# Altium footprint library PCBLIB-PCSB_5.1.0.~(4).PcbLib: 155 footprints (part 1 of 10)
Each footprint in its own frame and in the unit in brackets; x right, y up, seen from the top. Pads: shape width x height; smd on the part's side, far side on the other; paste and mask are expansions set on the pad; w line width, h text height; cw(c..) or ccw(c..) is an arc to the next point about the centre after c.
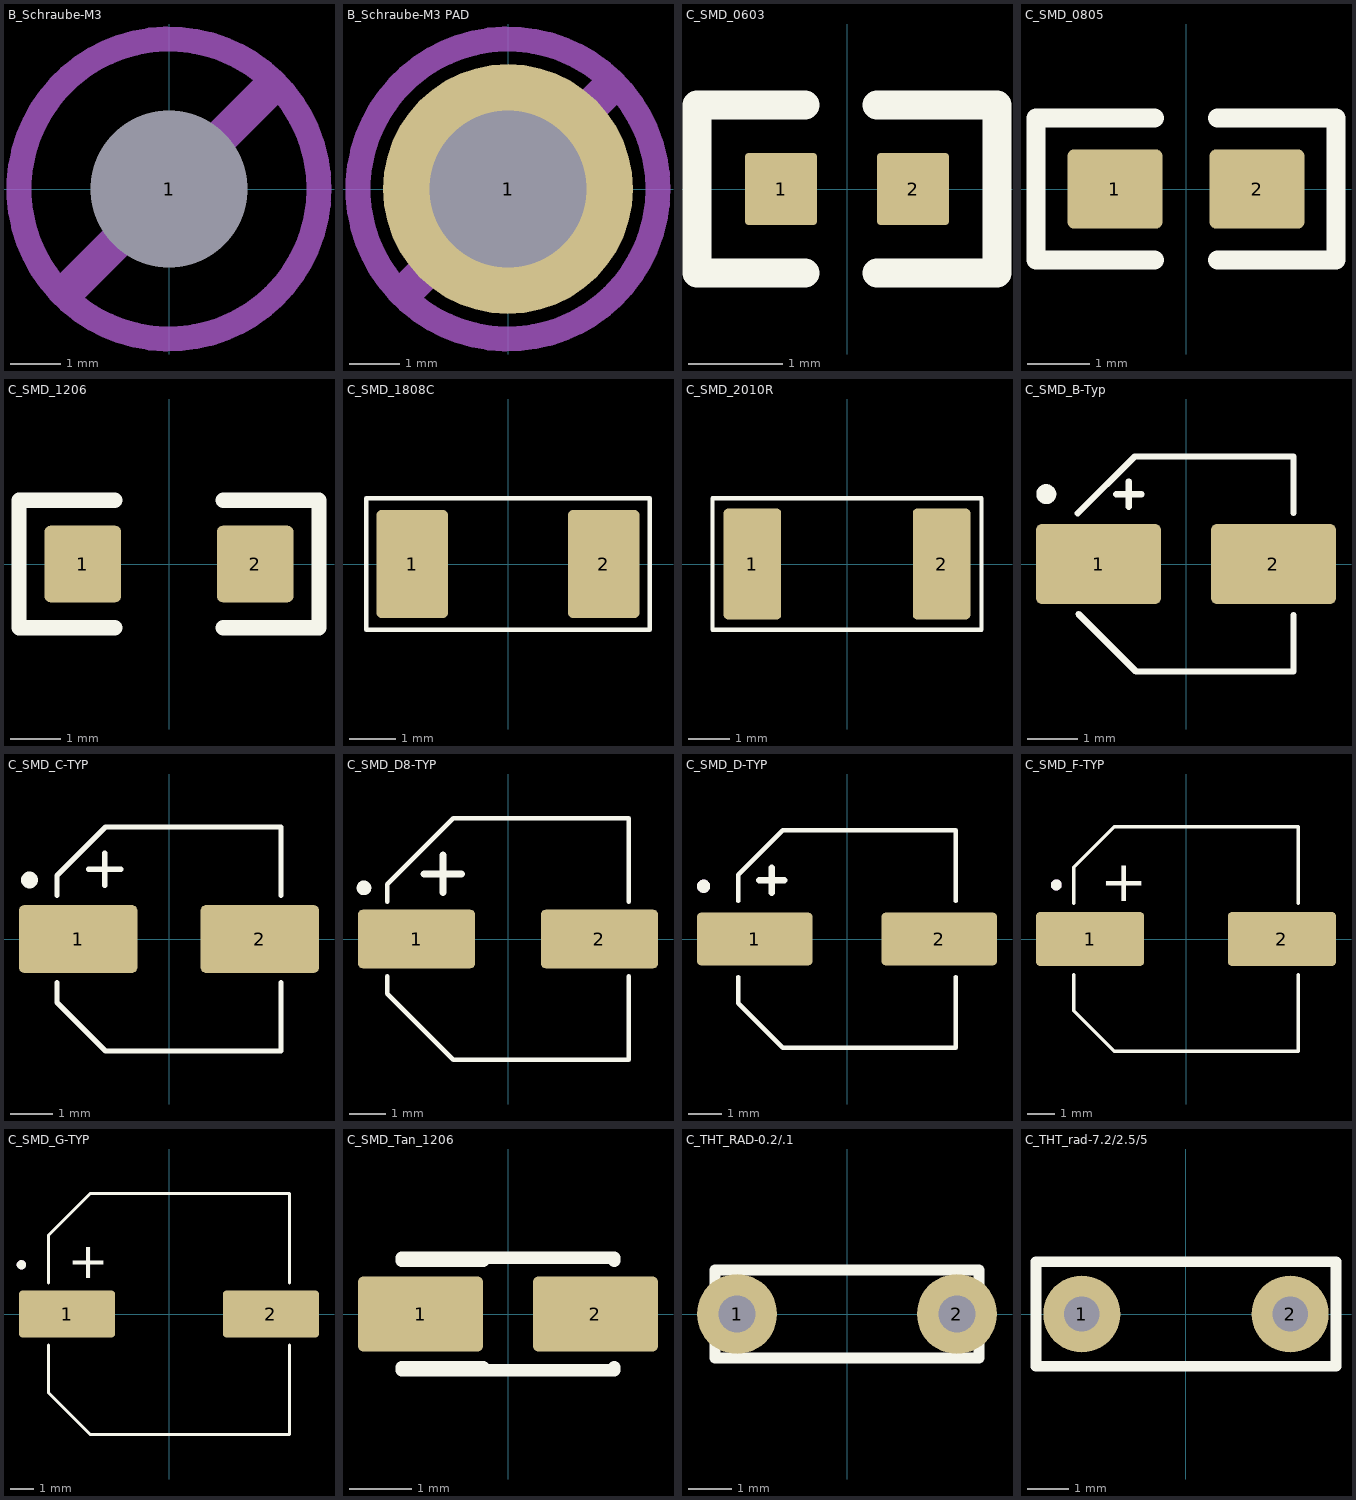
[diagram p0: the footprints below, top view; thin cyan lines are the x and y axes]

## B_Schraube-M3 [mm] "LB-2024-04-18"
pads (1):
  round 0.75 hole 3.15 unplated: 1(0,0)
Mechanical 1:
  circle w0.5: c0,0 r3
  lines w0.7: -2,-2 2,2

## B_Schraube-M3 PAD [mm] "LB-2024-04-18"
pads (1):
  round 5 hole 3.15 unplated: 1(0,0)
Mechanical 1:
  circle w0.5: c0,0 r3
  lines w0.7: -2,-2 2,2

## C_SMD_0603 [mil] "LB-2024-04-17"
pads (2):
  rrect10% 30x30 smd paste-0.79 mask+1.97: 1(-27.5,0) 2(27.5,0)
Top Overlay:
  lines w12: -17.5,-35 -62.5,-35 -62.5,35 -17.5,35 ; 12.5,-35 62.5,-35 62.5,35 12.5,35

## C_SMD_0805 [mil] "LB-2024-04-17"
pads (2):
  rrect15% 60x50 smd paste-0.79 mask+1.97: 1(-45,0) 2(45,0)
Top Overlay:
  lines w12: -20,-45 -95,-45 -95,45 -20,45 ; 20,-45 95,-45 95,45 20,45

## C_SMD_1206 [mil] "LB-2024-04-17"
pads (2):
  rrect15% 60x60 smd paste-0.79 mask+1.97: 1(-67.5,0) 2(67.5,0)
Top Overlay:
  lines w12: -42.5,-50 -117.5,-50 -117.5,50 -42.5,50 ; 42.5,-50 117.5,-50 117.5,50 42.5,50

## C_SMD_1808C [mm] "LB-2024-04-17"
height 2
pads (2):
  rrect15% 1.55x2.35 smd paste-0.02 mask+0.05: 1(-2.075,0) 2(2.075,0)
Top Overlay:
  lines w0.1: -3.075,-1.425 3.075,-1.425 3.075,1.425 -3.075,1.425 -3.075,-1.425

## C_SMD_2010R [mm] "LB-2024-04-17"
height 0.7
pads (2):
  rrect15% 1.4x2.7 smd paste-0.02 mask+0.05: 1(-2.3,0) 2(2.3,0)
Top Overlay:
  lines w0.1: -3.275,-1.6 -3.275,1.6 3.275,1.6 3.275,-1.6 -3.275,-1.6

## C_SMD_B-Typ [mm] "LB-2024-04-16"
pads (2):
  rrect15% 2.5x1.6 smd paste-0.02 mask+0.05: 1(-1.75,0) 2(1.75,0)
Top Overlay:
  circle w0.2: c-2.794,1.397 r0.1
  lines w0.127: -2.163,1.012 -1.025,2.15 2.15,2.15 2.15,1.025 ; -2.15,-1 -1,-2.15 2.15,-2.15 2.15,-1.025 ; -1.397,1.397 -0.889,1.397 ; -1.143,1.143 -1.143,1.651

## C_SMD_C-TYP [mm] "LB-2024-04-15"
pads (2):
  rrect15% 2.8x1.6 smd paste-0.02 mask+0.05: 1(-2.15,0) 2(2.15,0)
Top Overlay:
  circle w0.2: c-3.302,1.397 r0.1
  lines w0.127: -2.65,-1.033 -2.65,-1.5 -1.5,-2.65 2.65,-2.65 2.65,-1.033 ; -2.65,1.033 -2.65,1.5 ; -1.905,1.651 -1.143,1.651 ; -1.524,1.27 -1.524,2.032 ; 2.65,1.033 2.65,2.65 -1.5,2.65 ; -2.65,1.5 -1.5,2.65 ; -2.65,1.5 -1.5,2.65
3D body "EEE-FN1E470R.stp": height 0, standoff 0, extent 0,0 0,0

## C_SMD_D8-TYP [mm] "LB-2024-04-16"
pads (2):
  rrect15% 3.2x1.6 smd paste-0.02 mask+0.05: 1(-2.5,0) 2(2.5,0)
Top Overlay:
  circle w0.2: c-3.937,1.397 r0.1
  lines w0.127: -3.3,-1.018 -3.3,-1.5 -1.5,-3.3 3.3,-3.3 3.3,-1.018 ; -3.3,1.018 -3.3,1.5 -1.5,3.3 3.3,3.3 3.3,1.018
  lines w0.2: -2.286,1.778 -1.27,1.778 ; -1.778,1.27 -1.778,2.286
3D body "EEE-FK0J331XP.stp": height 0, standoff 0, extent 0,0 0,0

## C_SMD_D-TYP [mm] "LB-2024-04-16"
pads (2):
  rrect15% 3.5x1.6 smd paste-0.02 mask+0.05: 1(-2.8,0) 2(2.8,0)
Top Overlay:
  circle w0.2: c-4.35,1.6 r0.1
  lines w0.127: -3.3,-1.15 -3.3,-1.95 -1.95,-3.3 3.3,-3.3 3.3,-1.15 ; -3.3,1.15 -3.3,1.95 -1.95,3.3 3.3,3.3 3.3,1.15
  lines w0.2: -2.667,1.778 -1.905,1.778 ; -2.286,1.397 -2.286,2.159
Mechanical 13:
  circle w0.2: c-4.35,1.6 r0.1

## C_SMD_F-TYP [mm] "LB-2024-04-16"
pads (2):
  rrect15% 4x2 smd paste-0.02 mask+0.05: 1(-3.55,0) 2(3.55,0)
Top Overlay:
  circle w0.2: c-4.8,2 r0.1
  lines w0.127: -4.15,-1.32 -4.15,-2.65 -2.65,-4.15 4.15,-4.15 4.15,-1.32 ; -4.15,1.32 -4.15,2.65 -2.65,4.15 4.15,4.15 4.15,1.32
  text "+" at -3.175,1.397 h1.52
Mechanical 13:
  circle w0.2: c-4.8,2 r0.1
3D body "step_temp.STEP": height 0, standoff 0, extent 0,0 0,0

## C_SMD_G-TYP [mm] "LB-2024-04-16"
height 10.2
pads (2):
  rrect15% 4.1x2 smd paste-0.02 mask+0.05: 1(-4.35,0) 2(4.35,0)
Top Overlay:
  circle w0.2: c-6.3,2.1 r0.1
  lines w0.127: -5.15,-1.32 -5.15,-3.35 -3.35,-5.15 5.15,-5.15 5.15,-1.32 ; -5.15,1.32 -5.15,3.35 -3.35,5.15 5.15,5.15 5.15,1.32
  text "+" at -4.318,1.524 h1.52
Mechanical 13:
  circle w0.2: c-6.3,2.1 r0.1

## C_SMD_Tan_1206 [mm] "LB-2024-04-25"
height 2.2
pads (2):
  rrect15% 2x1.2 smd paste-0.02 mask+0.05: 1(-1.4,0) 2(1.4,0)
Top Overlay:
  lines w0.2: -1.7,-0.9 1.7,-0.9 1.7,-0.85 ; -1.7,-0.85 -0.4,-0.85 ; -1.7,0.85 -0.4,0.85 ; -1.7,0.9 1.7,0.9 1.7,0.85

## C_THT_RAD-0.2/.1 [mm] "LB-2024-04-17"
pads (2):
  round 1.85 hole 0.85: 1(-2.54,0) 2(2.54,0)
Top Overlay:
  lines w0.254: -3.048,-1.016 3.048,-1.016 3.048,1.016 -3.048,1.016 -3.048,-1.016

## C_THT_rad-7.2/2.5/5 [mm] "LB-2024-04-17"
pads (2):
  round 1.85 hole 0.85: 1(-2.5,0) 2(2.5,0)
Top Overlay:
  lines w0.254: -3.6,-1.25 3.6,-1.25 3.6,1.25 -3.6,1.25 -3.6,-1.25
